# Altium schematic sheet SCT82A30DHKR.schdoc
size 127 x 101 mm
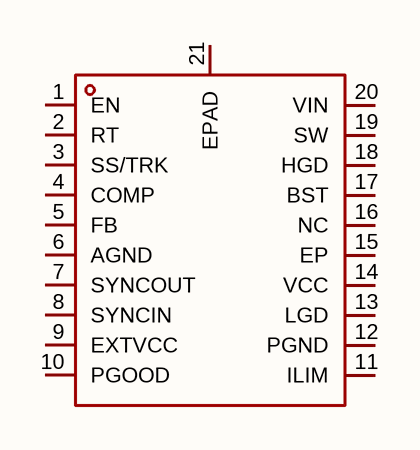
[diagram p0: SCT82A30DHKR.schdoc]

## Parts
U?  sct82a30dhkr  [VQFN-20_L4.5-W3.5-P0.50-BL-EP_TI_RHL0020A]  (value not drawn)

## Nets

Not connected (* = marked no-connect by the designer): U? 1(EN) 2(RT) 3(SS/TRK) 4(COMP) 5(FB) 6(AGND) 7(SYNCOUT) 8(SYNCIN) 9(EXTVCC) 10(PGOOD) 11(ILIM) 12(PGND) 13(LGD) 14(VCC) 15(EP) 16(NC) 17(BST) 18(HGD) 19(SW) 20(VIN) 21(EPAD)

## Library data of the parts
U? = sct82a30dhkr: 功能类型:降压型;工作电压:5.5V~100V;输出电压:800mV~60V;输出电流:2.3A；3.5A;输出类型:可调;; Manufacturer: SCT(芯洲科技); AddInBom: yes; ModelId: 29f0d93e7c9d4f7e9babd36c82b5f20b; ModelName: VQFN-20_L4.5-W3.5-H1.0-P0.50-BL-EP_BQ24100RHLR; ModelTransform: 137.795,177.165,0,90,0,0,0,0,0; Function: 降压型; Frequency - Switching: 780kHz; Synchronous Rectifier: 是; Number of Outputs: 1; Topology: 降压式; Quiescent Current: 1.5mA; Switch tube (built-in/external): 外置; Output Type: 可调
